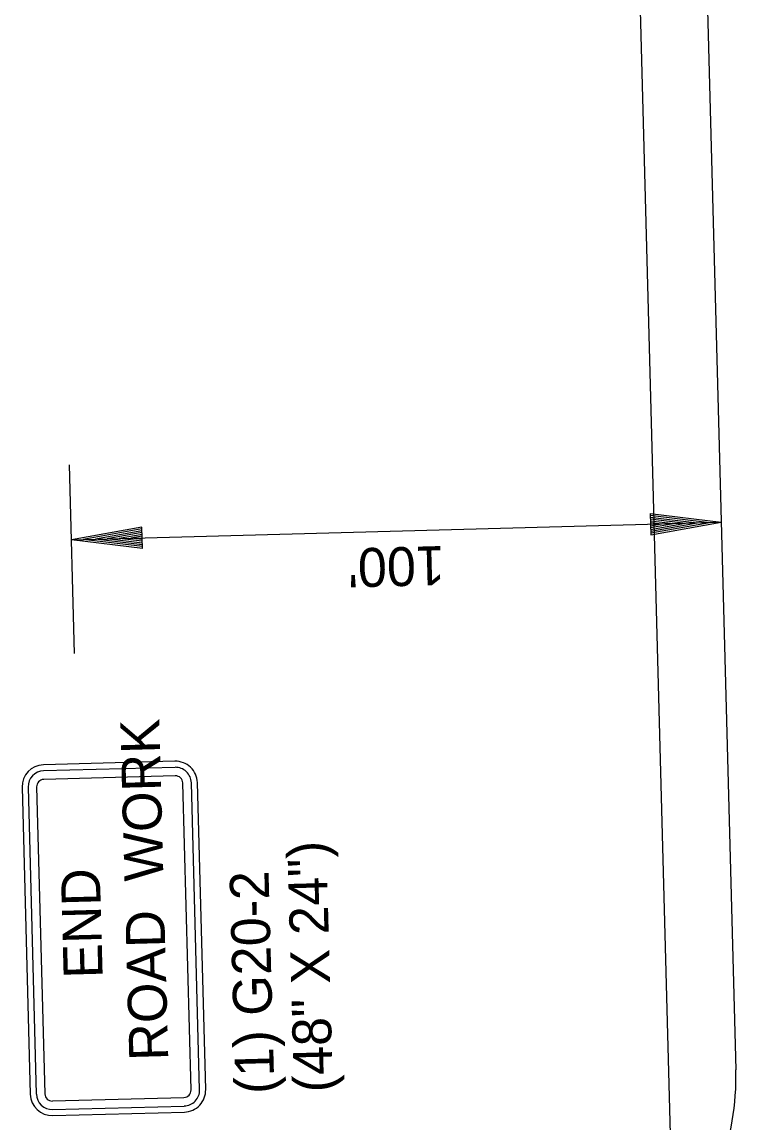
# Model space of a CAD drawing. Extents: x 1929653 to 1931621, y 596452 to 600944.
# Drawn here: x 1930771.1 to 1930935.8, y 597534.7 to 597788.5 of the extents above; entities that cross this region are included whole.
import ezdxf

# ---------------------------------------------------------------- set-up
doc = ezdxf.new("R2010")
doc.units = 0
for name, color, linetype in [('P_TC_Signs_Temporary', 7, 'Continuous'), ('R_Border', 7, 'Continuous'), ('R_Draft', 7, 'Continuous')]:
    doc.layers.add(name, color=color, linetype=linetype)

msp = doc.modelspace()

# ---------------------------------------------------------------- linework, layer by layer
at = {"layer": 'P_TC_Signs_Temporary'}
for p, q in [((1930806.34, 597617.92), (1930775.98, 597617.1)), ((1930806.38, 597616.51), (1930776.02, 597615.7)), ((1930806.43, 597614.55), (1930776.07, 597613.73)), ((1930810.07, 597542.06), (1930808.17, 597612.9)), ((1930812.04, 597542.11), (1930810.13, 597612.96)), ((1930813.44, 597542.15), (1930811.54, 597613)), ((1930771.06, 597611.91), (1930772.96, 597541.06)), ((1930772.46, 597611.95), (1930774.36, 597541.1)), ((1930774.43, 597612), (1930776.33, 597541.15)), ((1930778.06, 597539.51), (1930808.43, 597540.32)), ((1930778.12, 597537.54), (1930808.48, 597538.35)), ((1930778.15, 597536.13), (1930808.52, 597536.95))]:
    msp.add_line(p, q, dxfattribs=at)
for centre, radius, start, end in [((1930806.48, 597612.86), 5.06, 1.5377, 91.5377), ((1930776.12, 597612.04), 5.06, 91.5377, 181.5377), ((1930776.12, 597612.04), 3.66, 91.5377, 181.5377), ((1930806.48, 597612.86), 3.66, 1.5377, 91.5377), ((1930776.12, 597612.04), 1.69, 91.5377, 181.5377), ((1930806.48, 597612.86), 1.69, 1.5377, 91.5377), ((1930808.38, 597542.01), 1.69, 271.5377, 1.5377), ((1930808.38, 597542.01), 3.66, 271.5377, 1.5377), ((1930808.38, 597542.01), 5.06, 271.5377, 1.5377), ((1930778.02, 597541.19), 5.06, 181.5377, 271.5377), ((1930778.02, 597541.19), 3.66, 181.5377, 271.5377), ((1930778.02, 597541.19), 1.69, 181.5377, 271.5377)]:
    msp.add_arc(centre, radius, start, end, dxfattribs=at)
at = {"layer": 'R_Draft'}
for p, q in [((1930900.94, 598265.48), (1930925.44, 597352.83)), ((1930916.49, 598265.9), (1930935.8, 597546.71)), ((1930783.16, 597642.82), (1930782, 597686.34)), ((1930916.03, 597675.09), (1930932.41, 597673.08)), ((1930916.03, 597675.09), (1930916.15, 597670.2)), ((1930916.04, 597674.69), (1930929.68, 597673.01)), ((1930916.05, 597674.27), (1930926.88, 597672.94)), ((1930916.06, 597673.86), (1930924.16, 597672.86)), ((1930782.46, 597669.06), (1930932.41, 597673.08)), ((1930798.71, 597671.94), (1930782.46, 597669.06)), ((1930798.72, 597671.53), (1930785.19, 597669.14)), ((1930798.73, 597671.11), (1930787.99, 597669.21)), ((1930798.84, 597667.05), (1930798.71, 597671.94)), ((1930916.07, 597673.44), (1930921.39, 597672.79)), ((1930916.08, 597673.03), (1930918.66, 597672.71)), ((1930916.1, 597672.27), (1930918.66, 597672.71)), ((1930916.11, 597671.85), (1930921.39, 597672.79)), ((1930916.12, 597671.44), (1930924.16, 597672.86)), ((1930916.13, 597671.03), (1930926.88, 597672.94)), ((1930916.14, 597670.61), (1930929.68, 597673.01)), ((1930916.15, 597670.2), (1930932.41, 597673.08)), ((1930798.84, 597667.05), (1930782.46, 597669.06)), ((1930798.83, 597667.45), (1930785.19, 597669.14)), ((1930798.82, 597667.87), (1930787.99, 597669.21)), ((1930798.74, 597670.71), (1930790.71, 597669.28)), ((1930798.8, 597668.28), (1930790.71, 597669.28)), ((1930798.76, 597670.29), (1930793.47, 597669.35)), ((1930798.79, 597668.7), (1930793.47, 597669.35)), ((1930798.77, 597669.88), (1930796.2, 597669.43)), ((1930798.79, 597669.11), (1930796.2, 597669.43))]:
    msp.add_line(p, q, dxfattribs=at)
msp.add_arc((1930875.82, 597545.1), 60, 271.5377, 1.5377, dxfattribs=at)

# ---------------------------------------------------------------- texts
at = {"layer": 'P_TC_Signs_Temporary'}
for s, p in [('ROAD  WORK', (1930804.82, 597548.91)), ('END', (1930789.68, 597567.91))]:
    msp.add_text(s, height=9, rotation=91.5377, dxfattribs=at).set_placement(p)
at = {"layer": 'R_Border'}
for s, rotation, p in [("100'", 181.5377, (1930868.51, 597667.62)), ('(48" X 24")', 91.5377, (1930842.82, 597541.6)), ('(1) G20-2', 91.5377, (1930829.32, 597541.24))]:
    msp.add_text(s, height=9, rotation=rotation, dxfattribs=at).set_placement(p)

doc.saveas('drawing.dxf')
